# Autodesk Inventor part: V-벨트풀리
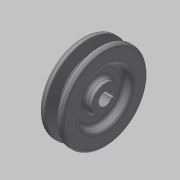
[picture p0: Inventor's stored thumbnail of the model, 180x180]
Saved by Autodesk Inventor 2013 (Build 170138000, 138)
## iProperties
Created: 2015-02
Part Number: V-벨트풀리
Material: 일반
Document SubType Name: Modeling
Designer: Administrator
Density: 1 g/cm^3
Author: Administrator
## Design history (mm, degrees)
sketch "스케치1"
  geometry: L1 (0, 0)-(25, 0); L2 (0, 5.5)-(25, 5.5); L3 (25, 5.5)-(25, 11); L4 (25, 11)-(13, 11); L5 (13, 11)-(13, 21.5); L6 (13, 21.5)-(19, 21.5); L7 (19, 21.5)-(19, 35.2); L8 (19, 35.2)-(14.325, 35.2); L9 (14.325, 35.2)-(11.574, 26.2); L10 (11.574, 26.2)-(7.426, 26.2); L11 (7.426, 26.2)-(4.675, 35.2); L12 (4.675, 35.2)-(0, 35.2); L13 (0, 35.2)-(0, 21.5); L14 (0, 21.5)-(6, 21.5); L15 (6, 21.5)-(6, 11); L16 (6, 11)-(0, 11); L17 (0, 11)-(0, 5.5); L18 (-9.302, 32.5)-(27.261, 32.5); L19 (9.5, 40.891)-(9.5, -3.941); 5 further points
  constraints: 38 end point, 13 parallel, 4 point on line, 3 collinear, 3 midpoint, 3 perpendicular, 3 vertical alignment, 1 horizontal, 1 other
  dimensions: "d0" = 25 distance of L1.start L1.end; "d1" = 11 diameter of L2 L1; "d2" = 22 diameter of L16 L1; "d3" = 6 distance of L15.end L16.end; "d5" = 6 distance of L5.end L6.end; "d6" = 43 diameter of L14 L1; "d7" = 65 diameter of L18 L1; "d8" = 70.4 diameter of L12 L1; "d9" = 19 distance between parallel lines of L7 L13; "d10" = 9.5 distance between parallel lines of L13 L19; "d11" = 34 deg angle of L9 L11; "d12" = 8 distance of point (13.5, 32.5) point (5.5, 32.5); "d13" = 6.3 distance between parallel lines of L18 L10
revolve "회전1" sketch "스케치1" stored, may be unused: angle "d14" = 90 deg
fillet "모깎기1" dims "d15" = 1
fillet "모깎기2" dims "d16" = 0.5
fillet "모깎기3" dims "d17" = 2
sketch "스케치2"
  geometry: L1 (-2, 7.3)-(2, 7.3); L2 (2, 7.3)-(2, 3.3); L3 (2, 3.3)-(-2, 3.3); L4 (-2, 3.3)-(-2, 7.3); C1 r 11 at (0, 0) reference
  constraints: 8 end point, 2 parallel, 1 horizontal, 1 perpendicular
  dimensions: "d18" = 4 distance of L2.end L3.end; "d19" = 4 distance of L1.end L2.end; "d20" = 2 distance from line of C1.centre L4; "d22" = 7.3 distance from line of C1.centre L1
extrude "돌출1" cut sketch "스케치2" stored distance "d23" = 10; taper "d24" = 0 deg
fillet "모깎기4" dims "d25" = 3
fillet "모깎기5" dims "d26" = 3
node "솔리드1"
